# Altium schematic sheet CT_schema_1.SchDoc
size 434 x 315 mm
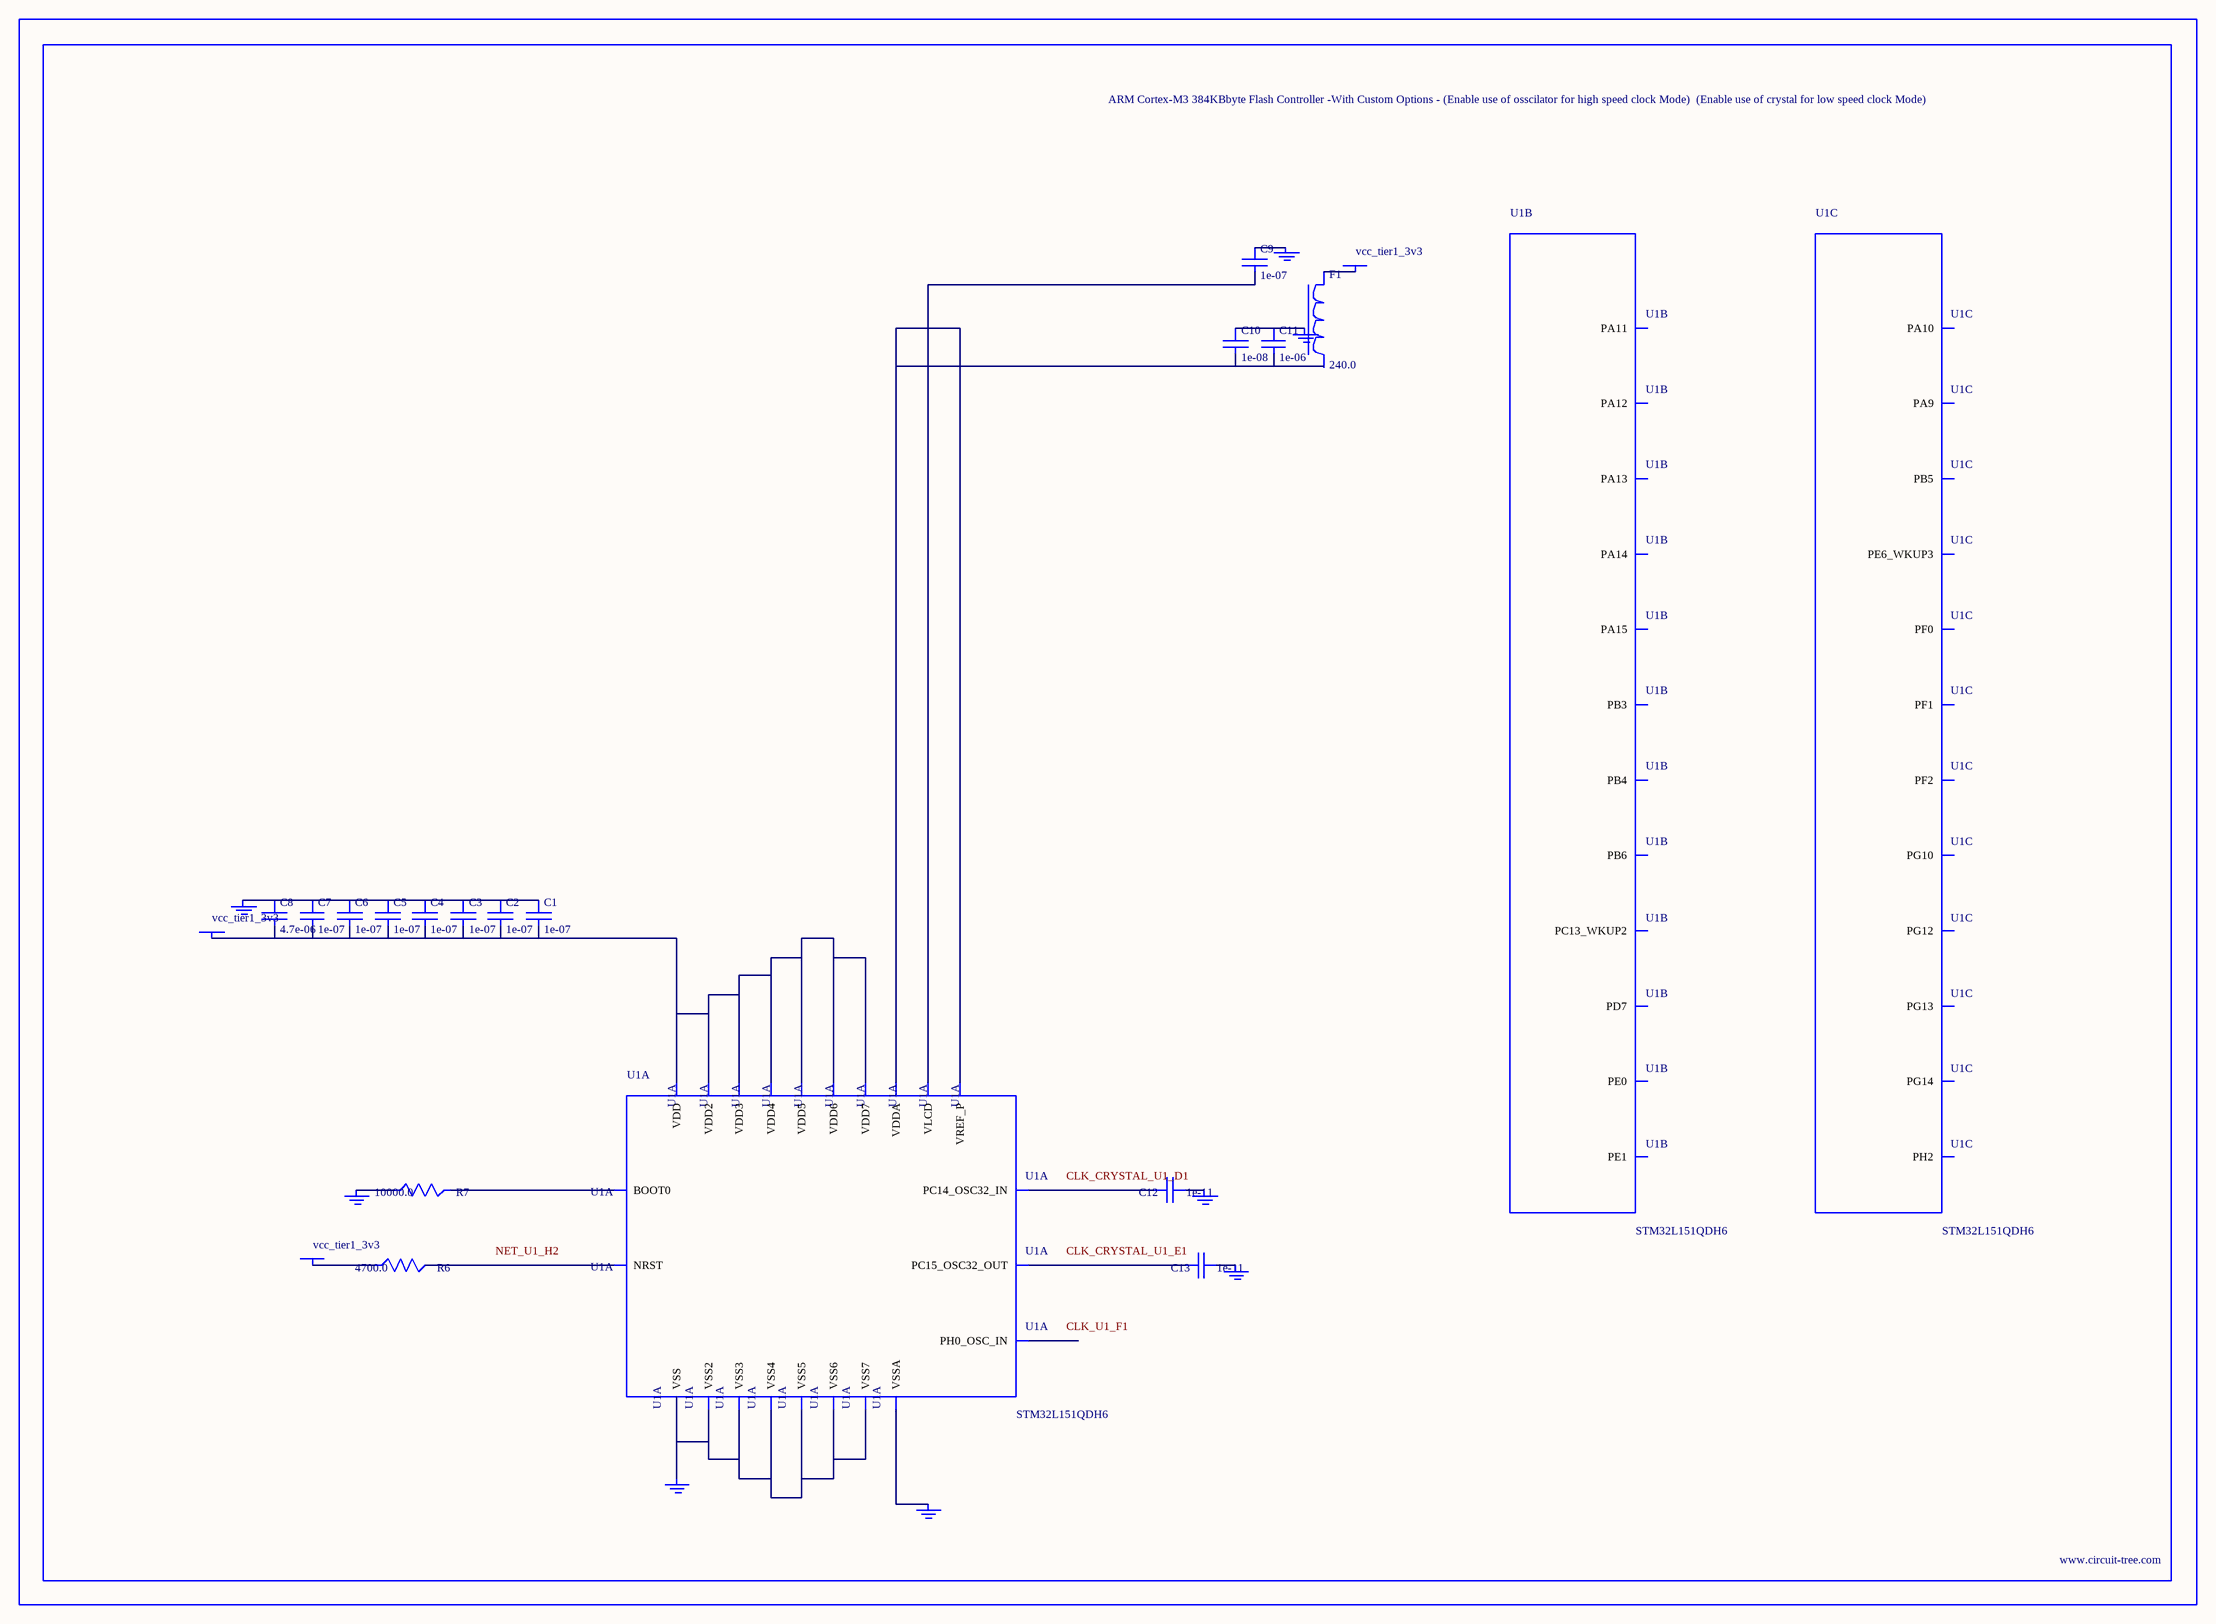
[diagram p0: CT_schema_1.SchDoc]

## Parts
BORDER0  (no value)
C1  1e-07  [C0603]
C2  1e-07  [C0603]
C3  1e-07  [C0603]
C4  1e-07  [C0603]
C5  1e-07  [C0603]
C6  1e-07  [C0603]
C7  1e-07  [C0603]
C8  4.7e-06  [C0603]
C9  1e-07  [C0603]
C10  1e-08  [C0603]
C11  1e-06  [C0603]
C12  1e-11  [C0402]
C13  1e-11  [C0402]
F1  240.0  [L0603]
GND_INSTANCE_0_0  (no value)
GND_INSTANCE_0_1  (no value)
GND_INSTANCE_0_2  (no value)
GND_INSTANCE_0_3  (no value)
GND_INSTANCE_0_4  (no value)
GND_INSTANCE_0_5  (no value)
GND_INSTANCE_0_6  (no value)
GND_INSTANCE_0_7  (no value)
POWER_INSTANCE_0_0  vcc_tier1_3v3
POWER_INSTANCE_0_1  vcc_tier1_3v3
POWER_INSTANCE_0_2  vcc_tier1_3v3
R6  4700.0  [R0603]
R7  10000.0  [R0603]
U1  STM32L151QDH6  [UFBGA132]  (parts A,B,C of 9)

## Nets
NetC1_1: C1.1 C2.1 C3.1 C4.1 C5.1 C6.1 C7.1 C8.1 GND_INSTANCE_0_1.0(GND)
NetC1_2: C1.2 C2.2 C3.2 C4.2 C5.2 C6.2 C7.2 C8.2 POWER_INSTANCE_0_1.0(PWR) U1.C4(VDD) U1.G2(VDD4) U1.G6(VDD5) U1.G7(VDD6) U1.G11(VDD2) U1.G12(VDD3) U1.H3(VDD7)
NetC9_1: C9.1 GND_INSTANCE_0_2.0(GND)
NetC9_2: C9.2 U1.E2(VLCD)
NetC10_1: C10.1 C11.1 GND_INSTANCE_0_0.0(GND)
NetC10_2: C10.2 C11.2 U1.L1(VREF_P) U1.M1(VDDA)
NetC12_1: C12.1 GND_INSTANCE_0_4.0(GND)
NetC12_2: C12.2 U1.D1(PC14_OSC32_IN)
NetC13_1: C13.1 GND_INSTANCE_0_5.0(GND)
NetC13_2: C13.2 U1.E1(PC15_OSC32_OUT)
NetF1_1: F1.1 POWER_INSTANCE_0_0.0(PWR)
NetGND_INSTANCE_0_3_0: GND_INSTANCE_0_3.0(GND) R7.1
NetGND_INSTANCE_0_6_0: GND_INSTANCE_0_6.0(GND) U1.J1(VSSA)
NetGND_INSTANCE_0_7_0: GND_INSTANCE_0_7.0(GND) U1.D3(VSS) U1.E3(VSS2) U1.F2(VSS5) U1.F6(VSS6) U1.F7(VSS7) U1.F11(VSS3) U1.F12(VSS4)
NetPOWER_INSTANCE_0_2_0: POWER_INSTANCE_0_2.0(PWR) R6.1
NetR6_2: R6.2 U1.H2(NRST)
NetR7_2: R7.2 U1.A4(BOOT0)

Not connected (* = marked no-connect by the designer): F1 2; U1 A2(PE1) A5(PD7) A7(PB4) A8(PB3) A9(PA15) A10(PA14) A11(PA13) A12(PA12) B5(PB6) B12(PA11) C1(PC13_WKUP2) C3(PE0) C5(PB5) C6(PG14) C7(PG13) C11(PH2) C12(PA10) D2(PE6_WKUP3) D4(PF2) D5(PF1) D6(PF0) D7(PG12) D8(PG10) D10(PA9) F1(PH0_OSC_IN)

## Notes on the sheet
- Labels drawn without touching a wire or pin: CLK_CRYSTAL_U1_D1, CLK_CRYSTAL_U1_E1, CLK_U1_F1, NET_U1_H2

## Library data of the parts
BORDER0 = BORDER_PAGE0
C1-C7 C9 = 06035C104K4Z2A
C8 = GRM188R6YA475KE15D
C10 = 06035C103K4Z2A
C11 = C0603C105K3RACTU
C12 C13 = C0402C100K3GACTU
F1 = Z0603C241ASMST
GND_INSTANCE_0_0-GND_INSTANCE_0_7 = GND
POWER_INSTANCE_0_0-POWER_INSTANCE_0_2 = PWR
R6 = RC0603JR-074K7L
R7 = RC0603JR-0710KL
